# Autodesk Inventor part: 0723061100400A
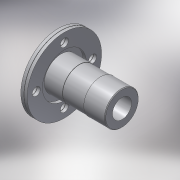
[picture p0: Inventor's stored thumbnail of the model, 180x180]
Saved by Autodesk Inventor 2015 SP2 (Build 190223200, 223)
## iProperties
Created: 2017-02
Part Number: 0723061100400A
Material: PVC-Piping
Description: PLASSON FLANGE ADAPTOR WITH METAL FLANGE 110-4"
Document SubType Name: Modeling
Designer: KIM
Mass: 92.6774 g
Surface Area: 199.44 cm^2
Volume: 66.1981 cm^3
Density: 1.4 g/cm^3
Appearance: Smooth - White
Author: Кирилл
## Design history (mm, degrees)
derived "872306.ipt"
feature "Solid1::872306.ipt"
tag "TaggingFeature1"
body "Solid1"
other parameters: "d73" = 21, "d74" = 90 deg, "d75" = 0.3, "d77" = 18, "d80" = 0, "d82" = 360 deg, "d96" = 0.3, "d99" = 360 deg, "d104" = 2.2, "d107" = 143, "d108" = 5.25, "d116" = 107.8, "d120" = 5.5, "S_" = 18
